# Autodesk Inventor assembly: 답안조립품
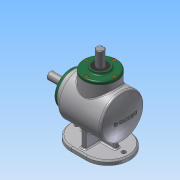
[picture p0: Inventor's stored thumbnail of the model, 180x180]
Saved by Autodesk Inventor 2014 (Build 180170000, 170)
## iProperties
Created: 2016-04
Part Number: 답안조립품
Document SubType Name: Assembly
Designer: 601-
Author: 601-
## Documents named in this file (14)
- C:\Users\601-\Desktop\460408V1008\답안조립품.iam
- C:\Users\601-\Desktop\460408V1008\본체.ipt
- C:\Users\601-\Desktop\460408V1008\커버.ipt
- C:\Users\601-\Desktop\460408V1008\베어링 6203.ipt
- C:\Users\601-\Desktop\460408V1008\오일실 17 32 8.ipt
- C:\Users\601-\Desktop\460408V1008\메인 축.ipt
- 메인 축.ipt
- C:\Users\601-\Desktop\460408V1008\키 4x4.ipt
- C:\Users\601-\Desktop\460408V1008\키 5x5.ipt
- C:\Users\601-\Desktop\460408V1008\서브 축.ipt
- 서브 축.ipt
- C:\Users\601-\Desktop\460408V1008\메인 베벨기어.ipt
- C:\Users\601-\Desktop\460408V1008\서브 베벨기어.ipt
- C:\Users\601-\Desktop\460408V1008\M4.ipt
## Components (8 placed, 1 different names)
1. M4:1
2. M4:3
3. M4:4
4. M4:5
5. M4:2
6. M4:6
7. M4:7
8. M4:8
